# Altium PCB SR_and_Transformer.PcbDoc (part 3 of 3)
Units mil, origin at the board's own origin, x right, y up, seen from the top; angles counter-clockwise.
Board outline 2362.61 x 1852.83 mil, 12 copper layers (Top Layer, Layer 1, Layer 2, Layer 3, Layer 4, Layer 5, Layer 6, Layer 7, Layer 8, Layer 9, Layer 10, Bottom Layer), stack 88.072 mil thick; 104 components, 44 nets, 388 pads, 1030 vias.
Unrouted connection lines stored in the file: 6.
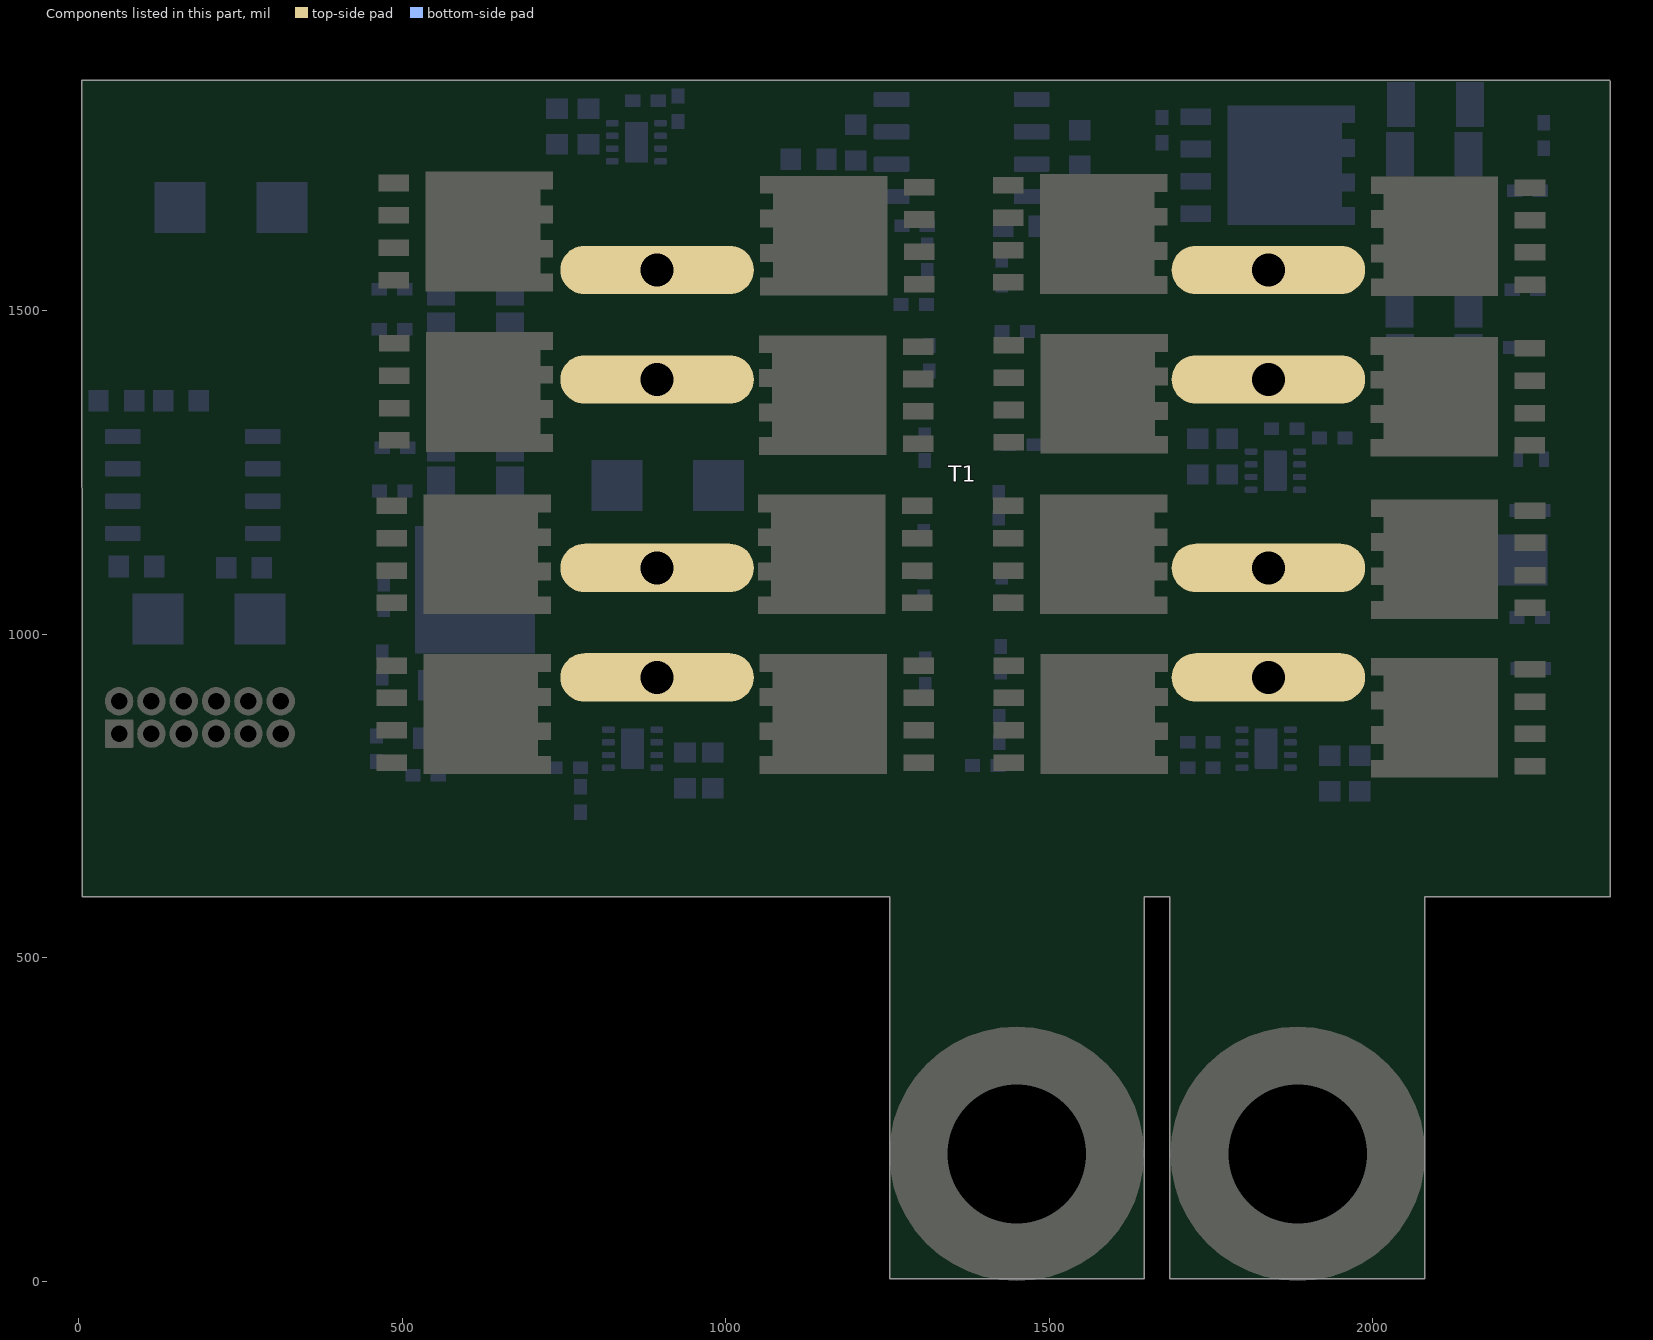
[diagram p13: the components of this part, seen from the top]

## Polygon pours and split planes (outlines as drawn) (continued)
SGND on Layer 1 "LAYER_1_SGND_P101" (solid, remove dead copper, pour order 101): 4.92,1856.87 4.92,597.03 1684.04,597.03 1686.92,594.15 1686.92,4.05 2080.2,4.05 2080.18,384.77 2080.18,594.6 2366.92,594.6 2366.92,1855.02
VSR on Layer 1 "LAYER_1_VSR_P013" (solid, remove dead copper, pour order 13): 1252.36,596.2 1253.96,594.6 1647.11,594.6 1647.11,4.05 1252.36,4.05
VSR on Layer 3 "LAYER_3_VSR_P016" (solid, remove dead copper, pour order 16): 1252.36,593.23 1253.73,594.6 1647.11,594.6 1647.11,4.05 1252.36,4.05
SGND on Layer 3 "LAYER_3_SGND_P103" (solid, remove dead copper, pour order 103): 4.92,1856.87 4.92,597.03 1684.04,597.03 1686.92,594.15 1686.92,4.05 2080.18,4.05 2080.18,382.77 2080.18,594.6 2362.35,594.6 2366.92,590.03 2366.92,1856.87
VSR on Layer 7 "LAYER_7_VSR_P077" (solid, remove dead copper, pour order 77): 731.09,1673.07 731.09,857.34 1124.35,857.38 1255.17,726.56 1255.17,4.05 1649.92,4.05 1649.92,592.35 1681.79,592.35 2000.54,911.1 2000.54,1412.86 1964.9,1448.5 1413.91,1448.5 1413.91,827.02 1384.26,797.38 1380.06,801.58 1354.61,801.58 1327.8,828.4 1338.13,838.73 1338.13,1612.26 1272.87,1677.52
SGND on Layer 7 "LAYER_7_SGND_P114" (solid, remove dead copper, pour order 114): 4.92,1856.87 4.92,594.6 1685.04,594.6 1686.92,592.72 1686.92,4.05 2080.18,4.05 2080.18,594.6 2366.92,594.6 2366.92,1856.87
SGND on Layer 2 "LAYER_2_SGND_P102" (solid, remove dead copper, pour order 102): 4.92,1856.87 4.92,594.6 5.37,594.15 1686.92,594.15 1686.92,4.05 2082.92,4.05 2082.92,591.63 2080.18,594.38 2366.92,594.38 2366.92,1856.87
VSR on Layer 2 "LAYER_2_VSR_P054" (solid, remove dead copper, pour order 54): 1252.36,593.23 1646.23,593.23 1647.11,592.35 1647.11,4.05 1252.36,4.05
SGND on Layer 6 "LAYER_6_SGND_P105" (solid, remove dead copper, pour order 105): 6.61,1856.87 2366,1856.87 2366,590.96 2366.92,590.03 2080.18,590.03 2080.18,4.05 1685.48,4.05 1685.48,592.72 1686.92,594.15 1686.48,594.6 4.92,594.6
VSR on Layer 6 "LAYER_6_VSR_P121" (solid, remove dead copper, pour order 121): 1255.17,593.23 1256.54,594.6 1649.92,594.6 1649.92,4.05 1255.17,4.05
VSR on Layer 4 "LAYER_4_VSR_P104" (solid, remove dead copper, pour order 104): 731.09,1673.07 731.09,857.34 1124.35,857.38 1255.17,726.55 1255.17,4.05 1649.92,4.05 1649.92,592.34 1681.79,592.34 2000.54,911.1 2000.54,1412.86 1964.9,1448.5 1413.91,1448.5 1413.91,827.02 1384.26,797.38 1380.06,801.58 1354.61,801.58 1327.8,828.4 1338.13,838.73 1338.13,1612.26 1272.87,1677.52
SGND on Layer 4 "LAYER_4_SGND_P128" (solid, remove dead copper, pour order 128): 5.81,1856.87 2366.92,1856.87 2366.92,594.6 2080.18,594.6 2082.92,591.85 2082.92,4.05 1684.04,4.05 1684.04,597.03 8.24,597.03 5.37,594.15
VSR on Layer 4 "LAYER_4_VSR_P057" (solid, remove dead copper, pour order 57): 1253.96,594.6 1647.11,594.6 1647.11,4.05 1249.54,4.05
SGND on Layer 5 "LAYER_5_SGND_P106" (solid, remove dead copper, pour order 106): 4.92,1856.87 4.92,594.6 5.37,594.15 1686.92,594.15 1686.92,4.05 2081.55,4.05 2081.55,593 2080.18,594.38 2366.92,594.38 2366.92,1857.8
VSR on Layer 5 "LAYER_5_VSR_P065" (solid, remove dead copper, pour order 65): 728.28,1673.07 728.28,857.34 1121.53,857.38 1252.36,726.55 1252.36,4.05 1647.11,4.05 1647.11,592.35 1678.97,592.35 1997.73,911.1 1997.73,1412.86 1962.09,1448.5 1411.1,1448.5 1411.1,827.02 1381.45,797.38 1377.25,801.58 1351.8,801.58 1324.98,828.4 1335.32,838.73 1335.32,1612.26 1270.05,1677.52
VSR on Layer 5 "LAYER_5_VSR_P058" (solid, remove dead copper, pour order 58): 1253.96,594.6 1255.77,592.79 1646.67,592.79 1646.67,4.05 1249.54,4.05
VSR on Layer 10 "LAYER_10_VSR_P123" (solid, remove dead copper, pour order 123): 728.28,1673.07 728.28,857.34 1121.53,857.38 1252.36,726.55 1252.36,4.05 1647.11,4.05 1647.11,592.35 1678.97,592.35 1997.73,911.1 1997.73,1412.86 1962.09,1448.5 1411.1,1448.5 1411.1,827.02 1381.45,797.38 1377.25,801.58 1351.8,801.58 1324.98,828.4 1335.32,838.73 1335.32,1612.26 1270.05,1677.52
VSR on Layer 10 "LAYER_10_VSR_P082" (solid, remove dead copper, pour order 82): 1249.54,593.23 1250.92,594.6 1644.3,594.6 1644.3,4.05 1249.54,4.05
SGND on Layer 10 "LAYER_10_SGND_P125" (solid, remove dead copper, pour order 125): 4.92,1856.87 4.92,597.03 1681.8,597.03 1682.92,598.16 1685.48,595.59 1685.48,4.05 2078.81,4.05 2082.92,8.16 2082.92,591.63 2359.39,591.63 2366,598.24 2366,1856.87
VSR on Bottom Layer "BOTTOM_LAYER_VSR_P120" (solid, remove dead copper, pour order 120): 718.61,1157.67 1097.26,1157.67 1097.26,983 718.61,983
T1 on Bottom Layer "BOTTOM_LAYER_T1_P119" (solid, remove dead copper, pour order 119): 1695.05,1173.56 2127.72,1173.56 2127.72,1056.56 2123.57,1052.41 1695.05,1052.41
T2 on Bottom Layer "BOTTOM_LAYER_T2_P118" (solid, remove dead copper, pour order 118): 733.55,1437.58 1040.02,1437.58 1067.99,1409.61 1067.4,1409.01 1067.4,1297.93 900.25,1297.93 888.29,1285.97 888.29,1160.91 778.67,1160.91 733.55,1206.03
VSR on Bottom Layer "BOTTOM_LAYER_VSR_P111" (solid, remove dead copper, pour order 111): 1494.89,1249.31 1495.14,1491.92 1989.2,1491.92 1989.2,1359.89 1705.12,1359.89 1686.48,1341.25 1686.48,1032.33 1503.95,1032.33 1494.07,1042.2
T1 on Bottom Layer "BOTTOM_LAYER_T1_P089" (solid, remove dead copper, pour order 89): 1441.22,1700.32 1581.52,1700.32 1663.65,1782.45 1770.86,1782.45 1770.86,1611.91 1768.58,1609.63 1997.73,1609.63 1997.73,1504.09 1493.22,1504.09 1446.86,1550.45 1440.52,1550.45
T2 on Bottom Layer "BOTTOM_LAYER_T2_P110" (solid, remove dead copper, pour order 110): 255.87,1180.98 255.32,1180.42 255.32,1082.02 338.2,1082.02 344.9,1088.72 344.9,1180.98
VSR on Bottom Layer "BOTTOM_LAYER_VSR_P109" (solid, remove dead copper, pour order 109): 736.05,1714.38 736.63,1714.95 968.99,1714.95 1099.75,1584.19 1252.36,1584.19 1252.36,950.34 1331.34,871.36 1331.34,741.57 1472.87,741.57 1476.72,745.43 1476.72,1267.47 1515.77,1267.47 1725.83,1057.41 1999.45,1057.41 1999.45,885.63 1709.61,885.63 1684.04,860.06 1684.04,597.03 1649.54,597.03 1646.67,594.16 1646.67,4.05 1252.36,4.05 1252.36,711.11 1249.54,713.92 1249.54,749.16 1226.3,772.4 1067.99,772.4 1067.99,1409.61 1040.02,1437.58 733.55,1437.58
SGND on Bottom Layer "BOTTOM_LAYER_SGND_P107" (solid, remove dead copper, pour order 107): 910.3,1288.31 899.8,1288.31 899.8,1161.49 899.22,1160.91 902.46,1157.67 1041.84,1157.67 1041.84,1265.06 1020.3,1286.6
VSR on Bottom Layer "BOTTOM_LAYER_VSR_P093" (solid, remove dead copper, pour order 93): 1252.36,593.23 1253.73,594.6 1647.11,594.6 1647.11,4.05 1252.36,4.05
SGND on Bottom Layer "BOTTOM_LAYER_SGND_P124" (solid, remove dead copper, pour order 124): 4.92,1856.87 4.92,597.03 1684.04,597.03 1684.04,6.92 1686.92,4.05 2080.18,4.05 2080.18,593 2081.55,594.38 2366.92,594.38 2366.92,1855.02
NetC18_1 on Bottom Layer "BOTTOM_LAYER_NETC18_1_P090" (solid, remove dead copper, pour order 90): 1775.14,1856.87 1765.71,1856.87 1766.16,1856.42 1766.16,1607.21 1995.32,1607.21 1997.73,1609.63 1997.73,1394.02 2090.24,1394.02 2104.21,1407.99 2104.21,1858.52
SGND on Bottom Layer "BOTTOM_LAYER_SGND_P088" (solid, remove dead copper, pour order 88): 1695.82,1350.59 1695.05,1349.82 1695.05,1226.09 1967.65,1226.09 1970.27,1223.48 1970.27,1349.73
NetC4_1 on Bottom Layer "BOTTOM_LAYER_NETC4_1_P087" (solid, remove dead copper, pour order 87): 612.9,1657.89 612.9,1186.83 605.98,1179.91 512.43,1179.91 512.43,968.83 514.25,970.66 713.85,970.66 713.85,1658.01 711.42,1660.44
T2 on Bottom Layer "BOTTOM_LAYER_T2_P086" (solid, remove dead copper, pour order 86): 550,964.35 550,892.92 572.02,870.9 1054.59,870.9 1054.59,983 742,983 723.35,964.35
SGND on Bottom Layer "BOTTOM_LAYER_SGND_P085" (solid, remove dead copper, pour order 85): 1695.91,847.06 1695.73,742.3 1993.19,742.3 1997.73,737.76 1998.92,738.94 1998.92,849.18
SGND on Bottom Layer "BOTTOM_LAYER_SGND_P083" (solid, remove dead copper, pour order 83): 716.31,861.38 711.42,856.49 711.42,735 1005.38,735 1013.43,743.05 1013.43,861.38
no net on Bottom Solder "NONET_L-01_P-001" (solid): 1497.6,1480.86 1980,1480.86 1980,1369.09 1980,1359.89 1694.62,1359.89 1685.24,1350.52 1685.24,1027.21 1501.92,1027.21
no net on Bottom Solder "NONET_L-01_P-001" (solid): 1230.71,597.61 1230.71,739.39 1212.65,757.44 1027.82,757.44 998.92,728.55 919.81,728.55 885.37,762.98 815.58,762.98 800.77,748.18 800.77,706.98 754.9,706.98 703.25,758.63 508.6,758.63 494.61,744.63 459.79,744.63 438.61,765.81 438.61,1674.66 401.95,1674.66 394.26,1666.98 394.26,1604.62 354.51,1564.87 354.51,810.02 6.77,810.02 4.85,808.1 4.92,808.04 4.92,597.03 1231.29,597.03
no net on Bottom Solder "NONET_L-01_P-001" (solid): 1647.11,571.65 1648.1,572.65 1648.1,848.57 1699.85,900.32 1991.42,900.32 1991.42,1049.59 1706.49,1049.59 1499.01,1257.07 1499.01,748.1 1482.45,731.54 1327.4,731.54 1327.4,854.56 1232.59,949.37 1232.59,1575.98 1112.09,1575.98 1090.18,1575.98 967.57,1698.59 745.64,1698.59 745.64,1446.65 1045.78,1446.65 1081.91,1410.52 1081.91,790.06 1221.44,790.06 1262.55,748.95 1262.55,603.74 1253.41,586.84
no net on Bottom Solder "NONET_L-01_P-001" (solid): 1686.92,591.28 1686.92,625.8 1821.55,760.43 1880.65,760.43 1912.53,728.55 1999.45,728.55 2029.52,758.62 2284.41,758.63 2284.41,1857.8 2366.92,1857.8 2366.92,594.6 2080.18,594.6 2080.18,590.03
no net on Top Solder "NONET_L-01_P-001" (solid): 4.86,797.63 5.22,798 383.01,798 383.01,608.54 4.92,608.54

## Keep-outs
Keep-Out Layer:
  text ".Layer_Name" at 577,-858.49 h60

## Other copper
Top Layer:
  text ".Layer_Name" at 577,-858.49 h60
Bottom Layer:
  text ".Layer_Name" at 577,-858.49 h60

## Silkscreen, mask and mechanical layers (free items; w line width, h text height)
Top Overlay:
  text ".Layer_Name" at 577,-858.49 h60
Bottom Overlay:
  lines w10: 1916.55,1332.03 1967.45,1332.03 1986,1313.47 1986,1312.97
  text "'.PRJ_Number'.PCB_Rev" at 258.55,1469.6 h30
  text ".Layer_Name" at 577,-858.49 h60
Top Paste:
  text ".Layer_Name" at 577,-858.49 h60
Bottom Paste:
  text ".Layer_Name" at 577,-858.49 h60
Top Solder:
  region: 363.16,1724.51 363.16,612.03 1379.04,612.03 1379.04,746.16 438.61,746.16 438.61,1723.44
  region: 1352.92,609.03 1346.71,615.25 1346.71,1771.81 1391.65,1771.81 1392.29,738.43 1686.92,738.43 1686.92,608.59
  region: 2295.92,1814.43 2295.92,740.36 1686.92,740.36 1686.92,595.04 1686.48,594.6 2366.92,594.6 2366.92,1814.45
  region: 1686.92,594.15 1686.92,4.05 2077.44,4.05 2077.44,591.85 2080.18,594.6
  region: 1253.41,594.6 1249.61,590.8 1249.61,4.05 1647.11,4.05 1647.11,594.6
  text ".Layer_Name" at 577,-858.49 h60
  text ".Layer_Name" at 577,-858.49 h60
Bottom Solder:
  region: 1686.92,594.15 1686.92,380.47 1686.92,4.05 2080.18,4.05 2080.18,594.6
  region: 1647.11,594.6 1251.25,594.6 1251.25,4.05 1647.11,4.05
  text ".Layer_Name" at 577,-858.49 h60
Drill Guide:
  text ".Layer_Name" at 577,-858.49 h60
M1 Board Outline:
  lines w10: 4.92,594.6 347.89,594.6 387.26,594.6 780.97,594.6 820.34,594.6 1214.04,594.6 1253.41,594.6 1253.41,4.05 1647.11,4.05 1647.11,594.6 1686.48,594.6 1686.48,4.05 2080.18,4.05 2080.18,594.6 2367.13,594.6 2366.94,1854.44 ; 4.92,597.03 4.52,1856.87 2366.72,1856.87
  text ".Layer_Name" at 577,-858.49 h60
M2 Board Dimensions:
  rectangle: 0,-275 125,-150
  rectangle: 125,-400 500,-275
  lines w7: 0,-275 1000,-275 ; 125,-400 125,-150 ; 250,-400 250,-150 ; 500,-400 500,-150 ; 750,-400 750,-150 ; 0,-400 1000,-400 1000,-150 0,-150 0,-400
  lines w10: 26.04,127.04 26.04,143 26.04,150.98 26.04,166.95 26.04,174.93 26.04,190.89 ; 1248.49,-59.51 1248.49,214.57
  text ".Layer_Name" at 577,-858.49 h60
M3 3D STEP Top:
  text ".Layer_Name" at 577,-858.49 h60
M4 3D STEP Bottom:
  text ".Layer_Name" at 577,-858.49 h60
M5 Assembly Top:
  lines w10: -292,-930.17 6308,-930.17 ; -292,-726.83 6310,-726.83 ; -292,-523.5 -292,-1133.5 3713,-1133.5 6310,-1133.5 6310,-523.5 -291.5,-523.5 -291.5,-1133.5 1284,-1133.5 ; 2173,-1133.5 2173,-523.5 ; 3440,-726.83 3440,-523.5 ; 4280,-726.83 4280,-523.5 ; 4902,-1140 4902,-937.17
  text "COMPONENTS MARKED 'DNP' SHOULD NOT BE POPULATED." at 1153.5,-318.5 h60
  text "ASSEMBLY VARIANT:" at 1153,-434 h60
  text ".VariantName" at 2189,-434 h60
  text "PCB VIEWED FROM TOP SIDE" at -228.5,-655.67 h60
  text "BOARD #:" at 2248,-655.67 h60
  text ".PRJ_Number" at 2793.5,-655.67 h60
  text "REV:" at 3638,-655.67 h60
  text ".PCB_Rev" at 3929.5,-655.67 h60
  text "SVN REV:" at 4476,-655.67 h60
  text ".VersionControl_RevNumber" at 4982,-655.67 h60
  text "TID #:" at 2248,-859 h60
  text ".TID" at 2793.5,-859 h60
  text "PLOT NAME =" at -228.5,-1064.34 h60
  text ".plot_File_Name" at 577,-1064.34 h60
  text "GENERATED    :" at 2250,-1064.34 h60
  text ".Print_Date" at 3119.5,-1064.34 h60
  text ".Print_Time" at 3848.5,-1064.34 h60
  text "TEXAS INSTRUMENTS" at 5113,-1064.34 h60
M6 Assembly Bottom:
  lines w10: -292.5,-727.33 6309.5,-727.33 ; -290.5,-930.67 6309.5,-930.67 ; 1115.5,-1140.5 1115.5,-937.67 ; 1737.5,-727.33 1737.5,-524 ; 2577.5,-727.33 2577.5,-524 ; 3844.5,-1134 3844.5,-524 ; 4733.5,-1134 6309,-1134 6309,-524 -292.5,-524 -292.5,-1134 2304.5,-1134 6309.5,-1134 6309.5,-524
  text "COMPONENTS MARKED 'DNP' SHOULD NOT BE POPULATED." at 6102,-318 h60
  text ".VariantName" at 5058,-434 h60
  text "ASSEMBLY VARIANT:" at 6097,-434 h60
  text ".VersionControl_RevNumber" at 1035.5,-656.17 h60
  text "SVN REV:" at 1541.5,-656.17 h60
  text ".PCB_Rev" at 2088,-656.17 h60
  text "REV:" at 2379.5,-656.17 h60
  text ".PRJ_Number" at 3224,-656.17 h60
  text "BOARD #:" at 3769.5,-656.17 h60
  text "PCB VIEWED FROM BOTTOM SIDE" at 6246,-656.17 h60
  text ".TID" at 3224,-859.5 h60
  text "TID #:" at 3769.5,-859.5 h60
  text "TEXAS INSTRUMENTS" at 904.5,-1064.84 h60
  text ".Print_Time" at 2169,-1064.84 h60
  text ".Print_Date" at 2898,-1064.84 h60
  text "GENERATED    :" at 3767.5,-1064.84 h60
  text ".plot_File_Name" at 5440.5,-1064.84 h60
  text "PLOT NAME =" at 6246,-1064.84 h60
M9 Title Sheet:
  drawing of 57 lines, arcs and shapes, not listed
  text "1" at 739.84,8036.5 h70
  text "2" at 3235.5,8036.5 h70
  text "3" at 5724.84,8036.5 h70
  text "4" at 8231.51,8036.5 h70
  text "5" at 10730.5,8036.5 h70
  text "6" at 13235.5,8036.5 h70
  text "A" at -416.5,6893.5 h70
  text "A" at 14383.5,6893.5 h70
  text "B" at -416.5,4513.5 h70
  text "B" at 14383.5,4513.5 h70
  text "C" at -416.5,2138.5 h70
  text "C" at 14383.5,2138.5 h70
  text "PROJECT TITLE:" at 11343.5,277.5 h45
  text ".PRJ_Title" at 11393.5,144.17 h70
  text "DESIGNED FOR:" at 11343.5,-23.5 h45
  text ".PRJ_Customer" at 11393.5,-163.5 h70
  text "D" at -416.5,-231.5 h70
  text "D" at 14383.5,-231.5 h70
  text "FILE NAME:" at 11343.5,-323.5 h45
  text ".PCB_File_Name_No_Path" at 11393.5,-443.5 h70
  text "Texas Instruments (TI) and/or its licensors do not warrant the accuracy or completeness of this specification" at 6374,-605.34 h45
  text "ENGINEER:" at 11343.5,-613.5 h45
  text "LAYOUT BY:" at 12848.5,-613.5 h45
  text "or any information contained therein. TI and/or its licensors do not warrant that this design will meet" at 6329.01,-718 h45
  text ".PRJ_Engineer" at 11393.5,-768.49 h70
  text ".PCB_Layout" at 12899,-768.49 h70
  text "the specifications, will be suitable for your application or fit for any particular purpose, or will operate in" at 6329.01,-830.67 h45
  text ".Layer_Name" at 577,-858.49 h60
  text "ALTIUM DESIGNER VERSION:" at 12848.5,-923.5 h45
  text "an implementation. TI and/or its licensors do not warrant that the design is production worthy. You should" at 6329.01,-943.33 h45
  text "completely validate and test your design implementation to confirm the system functionality for your application." at 6374,-1056 h45
  text ".print_Scale" at 11393.5,-1056.83 h70
  text ".Application_BuildNumber" at 12899,-1056.83 h70
  text "1" at 739.84,-1263.5 h70
  text "2" at 3235.5,-1263.5 h70
  text "3" at 5724.84,-1263.5 h70
  text "4" at 8231.51,-1263.5 h70
  text "5" at 10730.5,-1263.5 h70
  text "6" at 13235.5,-1263.5 h70
M10 Fab Notes:
  drawing of 189 lines, arcs and shapes, not listed
  text "DESIGN INFORMATION" at 12382.02,6356.17 h60
  text "MIN. TRACK WIDTH:" at 11737.46,6224.05 h60
  text "8" at 12833.7,6224.05 h60
  text "MIL" at 12988.46,6224.05 h60
  text "7.874" at 12667.32,6102.36 h60
  text "MIN. CLEARANCE:" at 11737.46,6099.92 h60
  text "MIL" at 12988.46,6099.92 h60
  text "MIN. VIA PAD SIZE:" at 11737.46,5975.8 h60
  text "24" at 12803.71,5975.8 h60
  text "MIL" at 12988.46,5975.8 h60
  text "0.05mm (2MIL)" at 12432.46,5845.9 h60
  text "MINIMUM ANNULAR RING" at 11408.23,5837.67 h60
  text "EXTERNAL" at 13140.46,5837.67 h60
  text "PER" at 11608.23,5727.55 h60
  text "IPC-D-275 CLASS 2 LEVEL C" at 11828.23,5727.54 h60
  text "MIL, HOLES" at 13316.46,5627.07 h60
  text "+/-" at 12924,5618.48 h60
  text "+/-" at 13778,5618.48 h60
  text "REGISTRATION TOLERANCES:" at 11408.23,5617.42 h60
  text "METAL" at 12608,5617.42 h60
  text "5" at 13184.2,5617.42 h60
  text "3" at 14017.2,5617.42 h60
  text "MIL" at 14133.46,5617.42 h60
  text "HOLE SIZE TOLERANCE (UNLESS OTHERWISE SPECIFIED):" at 11408.23,5519.1 h60
  text "+/-" at 13778,5516.23 h60
  text "3" at 14017.2,5515.17 h60
  text "MIL" at 14133.46,5515.17 h60
  text "MATERIAL:" at 11333.46,5377.52 h60
  text "FR-4 High Tg" at 12319.9,5249 h60
  text "X" at 12175.46,5241.01 h60
  text "FR-408" at 11754.46,5236.49 h60
  text "OTHER" at 13242.46,5236.49 h60
  text "62 MIL (1.6mm) +/-10%" at 12074.56,5093.46 h60
  text "X" at 11954.46,5091.01 h60
  text "THICKNESS:" at 11408.23,5085.24 h60
  text "OTHER" at 13359.46,5085.24 h60
  text "TOLERANCE:" at 11408.23,4946.92 h60
  text "X" at 12256.46,4946.92 h60
  text "ANSI IPC-6012 TYPE 3 CLASS 2" at 12434.48,4946.92 h60
  text "OTHER +/-" at 12434.46,4802.73 h60
  text "BOW & TWIST:" at 11408.23,4657.54 h60
  text "X" at 12256.46,4657.54 h60
  text "ANSI IPC-6012 TYPE 3 CLASS 2" at 12434.48,4657.54 h60
  text "OTHER +/-" at 12434.46,4510.85 h60
  text "DRILLING:" at 11333.46,4380.23 h60
  text "NC_DRILL FILES" at 13094.46,4275.04 h60
  text "REFERENCE:" at 11408.23,4271.1 h60
  text "X" at 12065.46,4271.01 h60
  text "AS SHOWN" at 12243.46,4271.1 h60
  text "X" at 12966.46,4271.1 h60
  text "OTHER" at 13392.46,4128.85 h60
  text "PTH COPPER THICKNESS:" at 11407.91,4125.32 h60
  text "X" at 12547.14,4125.32 h60
  text "20-30 um" at 12675.14,4125.32 h60
  text "BOARD FINISH:" at 11333.46,3977.73 h60
  text "SILKSCREEN:" at 11488.68,3867.6 h60
  text "X" at 12446.46,3867.6 h60
  text "TOP" at 12563.46,3867.6 h60
  text "X" at 12956.46,3867.6 h60
  text "BOTTOM" at 13074.46,3867.6 h60
  text "SILKSCREEN COLOR:" at 11488.68,3712.41 h60
  text "X" at 12445.46,3712.41 h60
  text "WHITE" at 12563.46,3712.41 h60
  text "OTHER" at 13074.46,3712.41 h60
  text "X" at 12576.46,3568.96 h60
  text "GREEN" at 12694.46,3568.96 h60
  text "OTHER" at 13312.46,3568.96 h60
  text "SOLDER RESIST COLOR:" at 11488.68,3562.1 h60
  text "X" at 12576.46,3414.71 h60
  text "MATTE" at 12694.46,3414.71 h60
  text "SEMI-GLOSS" at 13312,3414.07 h60
  text "IMMERSION GOLD (ENIG)" at 12394.46,3241.94 h60
  text "ENEPIG" at 13732,3234.72 h60
  text "SURFACE FINISH:" at 11333.46,3233.72 h60
  text "X" at 12216.46,3233.72 h60
  text "IMM. TIN/SILVER OR EQUIV" at 11663,3096.4 h60
  text "OTHER" at 13094.46,3092.47 h60
  text "ARRAY/PANEL:" at 11333.46,2937.09 h60
  text "CUT AND TRIM PER M1 BOARD OUTLINE" at 12394.46,2928.87 h60
  text "N.C. ROUTE" at 12394.46,2792.9 h60
  text "X" at 13082.46,2792.9 h60
  text "V. SCORE" at 13260.46,2792.9 h60
  text "CERTIFICATION:" at 11333.46,2663.77 h60
  text "MATERIALS AND WORKMANSHIP FOR ALL PCBS" at 12058.46,2663.77 h60
  text "TO MEET OR EXCEED THE REQUIREMENTS OF:" at 12058.46,2569.71 h60
  text "X" at 11695.97,2441.08 h60
  text "ANSI IPC-A-600F CLASS ->" at 11823.96,2441.08 h60
  text "X" at 13471.97,2441.08 h60
  text "2" at 13581.96,2441.08 h60
  text "1" at 13266.96,2439.58 h60
  text "3" at 13935.96,2439.58 h60
  text "X" at 12507.97,2293.39 h60
  text "RoHS" at 12635.96,2293.39 h60
  text "OTHER" at 13280.36,2293.39 h60
  text "PER ORDER" at 13677.42,2293.39 h60
  text "ALL BOARDS MUST MEET OR EXCEED UL94-V0 REQUIREMENTS." at 11361,2139.57 h60
  text "PCB MUST BEAR THE UL94V-0 UL REGISTERED MATERIAL ID NUMBER" at 11361,2023.5 h60
  text "ADDITIONAL REQUIREMENTS:" at 11333.46,1854.08 h60
  text "MICROSECTION:" at 11408.23,1746.95 h60
  text "YES" at 12313.96,1746.95 h60
  text "REQUIRED" at 13175.46,1602.62 h60
  text "BARE BOARD ELEC. TEST:" at 11408.23,1599.76 h60
  text "NONE" at 12713.96,1599.76 h60
  text "X" at 13057.46,1599.76 h60
  text "PER ORDER" at 13767.46,1599.76 h60
  text "XX MIL VIAS REQUIRE NON-CONDUCTIVE FILL AND PLANARIZE" at 11576.38,1394.82 h59
  text "XX MIL VIAS REQUIRE CONDUCTIVE FILL AND PLANARIZE" at 11584.38,1290.84 h60
  text "OUTER XX MIL TRACES REQUIRE 50 OHM SINGLE-ENDED IMPEDANCE" at 11583.39,1127.46 h58
  text "LAYER 2 & 3 (INNER LAYERS) XX MIL WIDE, XX MIL SPACE / TRACES REQUIRE 100 OHM DIFFERENTIAL IMPEDANCE" at 11575.39,891.74 h60
  text ".Layer_Name" at 577,-858.49 h60
M11 Gerber Information:
  lines w10: -292,-930.17 6308,-930.17 ; -292,-726.83 6310,-726.83 ; -292,-523.5 -292,-1133.5 3713,-1133.5 6310,-1133.5 6310,-523.5 -291.5,-523.5 -291.5,-1133.5 1284,-1133.5 ; 2173,-1133.5 2173,-523.5 ; 3440,-726.83 3440,-523.5 ; 4280,-726.83 4280,-523.5 ; 4902,-1140 4902,-937.17
  text "ALL ARTWORK VIEWED FROM TOP SIDE" at -228.5,-655.67 h60
  text "BOARD #:" at 2248,-655.67 h60
  text ".PRJ_Number" at 2793.5,-655.67 h60
  text "REV:" at 3638,-655.67 h60
  text ".PCB_Rev" at 3929.5,-655.67 h60
  text "SVN REV:" at 4476,-655.67 h60
  text ".VersionControl_RevNumber" at 4982,-655.67 h60
  text "LAYER NAME =" at -228.5,-858.49 h60
  text "TID #:" at 2248,-859 h60
  text ".TID" at 2793.5,-859 h60
  text "PLOT NAME =" at -228.5,-1064.34 h60
  text ".plot_File_Name" at 577,-1064.34 h60
  text "GENERATED    :" at 2250,-1064.34 h60
  text ".Print_Date" at 3119.5,-1064.34 h60
  text ".Print_Time" at 3848.5,-1064.34 h60
  text "TEXAS INSTRUMENTS" at 5113,-1064.34 h60
M12 Stackup:
  drawing of 711 lines, arcs and shapes, not listed
  text "Layer" at -133.6,7715.01 h60
  text "Name" at 276.31,7715.01 h60
  text "Material" at 1206.06,7715.01 h60
  text "Thickness" at 2065.82,7715.01 h60
  text "Constant" at 2715.66,7715.01 h60
  text "Board Layer Stack" at 3285.52,7715.01 h60
  text "Top Overlay" at 276.31,7595.01 h60
  text "Top Solder" at 276.31,7475.01 h60
  text "Solder Resist" at 1206.06,7475.01 h60
  text "0.40mil" at 2065.82,7475.01 h60
  text "3.5" at 2715.66,7475.01 h60
  text "1" at -133.6,7355.01 h60
  text "Top Layer" at 276.31,7355.01 h60
  text "CF-005" at 1206.06,7355.01 h60
  text "2.76mil" at 2065.82,7355.01 h60
  text "Dielectric 1" at 276.31,7235.01 h60
  text "FR-4 High Tg" at 1206.06,7235.01 h60
  text "5.00mil" at 2065.82,7235.01 h60
  text "4.5" at 2715.66,7235.01 h60
  text "2" at -133.6,7115.01 h60
  text "Layer 1" at 276.31,7115.01 h60
  text "CF-005" at 1206.06,7115.01 h60
  text "2.76mil" at 2065.82,7115.01 h60
  text "Dielectric 2" at 276.31,6995.01 h60
  text "FR-4 High Tg" at 1206.06,6995.01 h60
  text "5.00mil" at 2065.82,6995.01 h60
  text "4.5" at 2715.66,6995.01 h60
  text "3" at -133.6,6875.01 h60
  text "Layer 2" at 276.31,6875.01 h60
  text "CF-005" at 1206.06,6875.01 h60
  text "2.76mil" at 2065.82,6875.01 h60
  text "Dielectric 3" at 276.31,6755.01 h60
  text "FR-4 High Tg" at 1206.06,6755.01 h60
  text "5.00mil" at 2065.82,6755.01 h60
  text "4.5" at 2715.66,6755.01 h60
  text "4" at -133.6,6635.01 h60
  text "Layer 3" at 276.31,6635.01 h60
  text "CF-005" at 1206.06,6635.01 h60
  text "2.76mil" at 2065.82,6635.01 h60
  text "Dielectric 4" at 276.31,6515.01 h60
  text "FR-4 High Tg" at 1206.06,6515.01 h60
  text "5.00mil" at 2065.82,6515.01 h60
  text "4.5" at 2715.66,6515.01 h60
  text "5" at -133.6,6395.01 h60
  text "Layer 4" at 276.31,6395.01 h60
  text "CF-005" at 1206.06,6395.01 h60
  text "2.76mil" at 2065.82,6395.01 h60
  text "Dielectric 5" at 276.31,6275.01 h60
  text "Core-009" at 1206.06,6275.01 h60
  text "5.00mil" at 2065.82,6275.01 h60
  text "4.5" at 2715.66,6275.01 h60
  text "6" at -133.6,6155.01 h60
  text "Layer 5" at 276.31,6155.01 h60
  text "CF-005" at 1206.06,6155.01 h60
  text "2.76mil" at 2065.82,6155.01 h60
  text "Dielectric6" at 276.31,6035.01 h60
  text "FR-4 High Tg" at 1206.06,6035.01 h60
  text "5.00mil" at 2065.82,6035.01 h60
  text "4.8" at 2715.66,6035.01 h60
  text "7" at -133.6,5915.01 h60
  text "Layer 6" at 276.31,5915.01 h60
  text "CF-005" at 1206.06,5915.01 h60
  text "2.76mil" at 2065.82,5915.01 h60
  text "Dielectric 7" at 276.31,5795.01 h60
  text "Core-009" at 1206.06,5795.01 h60
  text "5.00mil" at 2065.82,5795.01 h60
  text "4.5" at 2715.66,5795.01 h60
  text "8" at -133.6,5675.01 h60
  text "Layer 7" at 276.31,5675.01 h60
  text "CF-005" at 1206.06,5675.01 h60
  text "2.76mil" at 2065.82,5675.01 h60
  text "Dielectric 8" at 276.31,5555.01 h60
  text "FR-4 High Tg" at 1206.06,5555.01 h60
  text "5.00mil" at 2065.82,5555.01 h60
  text "4.5" at 2715.66,5555.01 h60
  text "9" at -133.6,5435.01 h60
  text "Layer 8" at 276.31,5435.01 h60
  text "CF-005" at 1206.06,5435.01 h60
  text "2.76mil" at 2065.82,5435.01 h60
  text "Dielectric 9" at 276.31,5315.01 h60
  text "FR-4 High Tg" at 1206.06,5315.01 h60
  text "5.00mil" at 2065.82,5315.01 h60
  text "4.5" at 2715.66,5315.01 h60
  text "10" at -133.6,5195.01 h60
  text "Layer 9" at 276.31,5195.01 h60
  text "CF-005" at 1206.06,5195.01 h60
  text "2.76mil" at 2065.82,5195.01 h60
  text "Dielectric 10" at 276.31,5075.01 h60
  text "FR-4 High Tg" at 1206.06,5075.01 h60
  text "5.00mil" at 2065.82,5075.01 h60
  text "4.5" at 2715.66,5075.01 h60
  text "11" at -133.6,4955.01 h60
  text "Layer 10" at 276.31,4955.01 h60
  text "CF-005" at 1206.06,4955.01 h60
  text "2.76mil" at 2065.82,4955.01 h60
  text "Dielectric 11" at 276.31,4835.01 h60
  text "FR-4 High Tg" at 1206.06,4835.01 h60
  text "5.00mil" at 2065.82,4835.01 h60
  text "4.5" at 2715.66,4835.01 h60
  text "12" at -133.6,4715.01 h60
  text "Bottom Layer" at 276.31,4715.01 h60
  text "CF-005" at 1206.06,4715.01 h60
  text "2.76mil" at 2065.82,4715.01 h60
  text "Bottom Solder" at 276.31,4595.01 h60
  text "Solder Resist" at 1206.06,4595.01 h60
  text "0.40mil" at 2065.82,4595.01 h60
  text "3.5" at 2715.66,4595.01 h60
  text "Bottom Overlay" at 276.31,4475.01 h60
  text ".Layer_Name" at 577,-858.49 h60
M13 Component Bodies Top:
  text ".Layer_Name" at 577,-858.49 h60
M14 Component Bodies Bottom:
  text ".Layer_Name" at 577,-858.49 h60
M15 Courtyards Top:
  text ".Layer_Name" at 577,-858.49 h60
M16 Courtyards Bottom:
  text ".Layer_Name" at 577,-858.49 h60
Drill Drawing:
  circle w10: c5089.72,6814.34 r27.63
  lines w10: 5062.09,6662.39 5089.72,6676.21 5117.34,6662.39 5103.53,6690.02 5117.34,6717.65 5089.72,6703.83 5062.09,6717.65 5075.9,6690.02 5062.09,6662.39 ; 5062.09,6924.85 5075.9,6924.85 5089.72,6911.03 5103.53,6924.85 5117.34,6924.85 5103.53,6938.66 5117.34,6952.47 5103.53,6952.47 5089.72,6966.29 5075.9,6952.47 5062.09,6952.47 5075.9,6938.66 5062.09,6924.85 ; 5062.09,7090.61 5117.34,7090.61 5089.72,7035.35 5062.09,7090.61 ; 5062.09,7159.67 5117.34,7159.67 5117.34,7214.93 5062.09,7214.93 5062.09,7159.67
  lines w12: 5012,6625.1 8197,6625.1 ; 5012,7246.7 8197,7246.7 ; 5349.86,6500.78 5349.86,7371.02 ; 5679.14,6500.78 5679.14,7371.02 ; 6271.94,6500.78 6271.94,7371.02 ; 6531.08,6500.78 6531.08,7371.02 ; 6906.24,6500.78 6906.24,7371.02 ; 7630.57,6500.78 7630.57,7371.02 ; 5012,6500.78 8197,6500.78 8197,7371.02 5012,7371.02 5012,6500.78
  text "Symbol" at 5086.59,7283.99 h72
  text "Count" at 5387.16,7283.99 h72
  text "Hole Size" at 5716.44,7283.99 h72
  text "Plated" at 6309.23,7283.99 h72
  text "Hole Type" at 6568.38,7283.99 h72
  text "Drill Layer Pair" at 6943.53,7283.99 h72
  text "Hole Tolerance" at 7667.86,7283.99 h72
  text "9" at 5387.16,7159.67 h60
  text "7.87mil (0.200mm)" at 5716.44,7159.67 h60
  text "PTH" at 6309.23,7159.67 h60
  text "Round" at 6568.38,7159.67 h60
  text "Top Layer - Bottom Layer" at 6943.53,7159.67 h60
  text "1021" at 5387.16,7035.35 h60
  text "8.00mil (0.203mm)" at 5716.44,7035.35 h60
  text "PTH" at 6309.23,7035.35 h60
  text "Round" at 6568.38,7035.35 h60
  text "Top Layer - Bottom Layer" at 6943.53,7035.35 h60
  text "12" at 5387.16,6911.03 h60
  text "25.59mil (0.650mm)" at 5716.44,6911.03 h60
  text "PTH" at 6309.23,6911.03 h60
  text "Round" at 6568.38,6911.03 h60
  text "Top Layer - Bottom Layer" at 6943.53,6911.03 h60
  text "8" at 5387.16,6786.71 h60
  text "51.18mil (1.300mm)" at 5716.44,6786.71 h60
  text "PTH" at 6309.23,6786.71 h60
  text "Slot" at 6568.38,6786.71 h60
  text "Top Layer - Bottom Layer" at 6943.53,6786.71 h60
  text "2" at 5387.16,6662.39 h60
  text "214.57mil (5.450mm)" at 5716.44,6662.39 h60
  text "PTH" at 6309.23,6662.39 h60
  text "Round" at 6568.38,6662.39 h60
  text "Top Layer - Bottom Layer" at 6943.53,6662.39 h60
  text "1052 Total" at 5387.16,6538.07 h60
  text "Slot definitions :" at 5086.59,6451.05 h60
  text "Routed Path Length" at 5537.31,6451.05 h60
  text "= Calculated from tool start centre position to tool end centre position." at 6077.05,6451.05 h60
  text "Hole Length" at 5537.31,6401.32 h60
  text "= Routed Path Length + Tool Size = Slot length as defined in the PCB layout" at 5877.24,6401.32 h60
  text ".Layer_Name" at 577,-858.49 h60
M17 Embedded Cavity:
  text ".Layer_Name" at 577,-858.49 h60
M18 Embedded Assembly:
  text ".Layer_Name" at 577,-858.49 h60
M19 Embedded Keepout:
  text ".Layer_Name" at 577,-858.49 h60

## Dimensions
26.04,166.95 to 1248.49,214.57 on M2 Board Dimensions
1248.49,214.57 to 0,0 on M2 Board Dimensions
0,-400 to 1000,-400 on M2 Board Dimensions
0,0 to 1253.41,594.6 on M2 Board Dimensions
0,0 to 820.34,594.6 on M2 Board Dimensions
